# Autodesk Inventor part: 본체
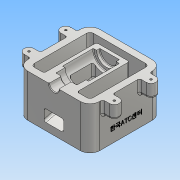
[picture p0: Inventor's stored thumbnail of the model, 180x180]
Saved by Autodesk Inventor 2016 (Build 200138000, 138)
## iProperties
Created: 2018-01
Part Number: 본체
Material: 알루미늄 6061
Document SubType Name: Modeling
Designer: Administrator
Density: 2.7 g/cm^3
Appearance: 알루미늄 - 평지
Mass: 995.217 g
Surface Area: 834.407 cm^2
Volume: 368.599 cm^3
Author: Administrator
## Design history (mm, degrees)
sketch "스케치1"
  geometry: L1 (-55, 55)-(55, 55); L2 (55, 55)-(55, -55); L3 (55, -55)-(-55, -55); L4 (-55, -55)-(-55, 55); L5 (-55, 55)-(55, -55); L6 (55, 55)-(-55, -55); 1 further point
  constraints: 12 end point, 2 midpoint, 2 parallel, 1 horizontal, 1 perpendicular
  dimensions: "d0" = 110 distance of L2.end L3.end; "d1" = 110 distance of L1.end L2.end
extrude "돌출1" new body sketch "스케치1" distance "d2" = 65; taper "d3" = 0 deg
feature "쉘1" dims "d4" = 10
sketch "스케치2"
  geometry: L1 (55, 55)-(-55, 55) reference; L2 (-45, -45)-(45, -45) reference; L3 (-25, 35)-(25, 35); L4 (25, 35)-(25, -45); L5 (25, -45)-(-25, -45); L6 (-25, -45)-(-25, 35); 2 further points
  constraints: 8 end point, 2 parallel, 1 horizontal, 1 midpoint, 1 perpendicular, 1 point on line, 1 vertical alignment
  dimensions: "d5" = 50 distance between parallel lines of L6 L4; "d6" = 20 distance between parallel lines of L3 L1
extrude "돌출2" join sketch "스케치2" distance "d7" = 65; taper "d8" = 0 deg
sketch "스케치3"
  geometry: L1 (-55, 0)-(55, 0) reference; L2 (-45, 0)-(-45, 8.564); L3 (-45, 8.564)-(35, 30); L4 (35, 65)-(35, 0) reference; L5 (-55, 0)-(-55, 65) reference; 1 further point
  constraints: 4 end point, 2 point on line, 1 vertical
  dimensions: "d9" = 30 distance from line of L1 L3.end; "d10" = 105 deg angle of L2 L3; "d11" = 10 distance between parallel lines of L5 L2
extrude "돌출3" cut sketch "스케치3" stored distance "d12" = 50; taper "d13" = 0 deg
sketch "스케치4"
  geometry: L1 (25, 35)-(-25, 35) reference; L2 (0, 35)-(0, -55); L3 (55, -55)-(-55, -55) reference; L4 (0, -55)-(-7.5, -55); L5 (-7.5, -36)-(-16, -36); L6 (-16, -36)-(-16, -22); L7 (-16, -22)-(-20, -22); L8 (-20, -22)-(-20, 25); L9 (-20, 25)-(-15, 25); L10 (-15, 25)-(-15, 30); L11 (-15, 30)-(0, 30); L12 (-7.5, -55)-(-7.5, -36); L13 (0, -55)-(-7.5, -55); 1 further point
  constraints: 22 end point, 6 perpendicular, 2 midpoint, 2 point on line, 1 collinear, 1 horizontal, 1 vertical
  dimensions: "d14" = 40 diameter of L8 L2; "d15" = 15 diameter of L12 L2; "d16" = 32 diameter of L6 L2; "d17" = 19 distance of L4.end L5.start; "d18" = 14 distance of L5.end L6.end; "d19" = 47 distance of L7.end L8.end; "d20" = 5 distance of L9.end L10.end; "d21" = 30 diameter of L10 L2
revolve "회전1" sketch "스케치4" stored, may be unused: angle "d22" = 90 deg
sketch "스케치5"
  geometry: L1 (-55, 55)-(-55, -55) reference; L2 (-55, -55)-(-7.5, -55) reference; L3 (-55, -20.5)-(-65, -20.5); L4 (-65, -20.5)-(-65, -35.5); L5 (-65, -35.5)-(-55, -35.5); L6 (-55, -35.5)-(-55, -20.5); A1 r 7.5 centre (-65, -28) between (-65, -20.5) and (-65, -35.5); 1 further point
  constraints: 8 end point, 2 parallel, 2 point on circle, 1 centre point, 1 horizontal, 1 midpoint, 1 perpendicular, 1 point on line
  dimensions: "d23" = 27 distance from line of L2 A1.centre; "d24" = 10 distance from line of L1 A1.centre; "d25" = 7.5 radius of A1
extrude "돌출4" join sketch "스케치5" distance "d26" = 20; taper "d27" = 0 deg
sketch "스케치6"
  geometry: A1 r 7.5 centre (-65, -28) between (-65, -20.5) and (-65, -35.5) reference; 2 further points
  constraints: 1 coincident
hole "구멍1" sketch "스케치6" at (-65, -28) diameter "d28" = 3.242; stored, may be unused: countersink angle "d32" = 90 deg, drill point angle "d34" = 118 deg; dims "d29" = 9, "d30" = 4, "d31" = 2, "d33" = 11
sketch "스케치7"
  geometry: L1 (-55, 11.061)-(20, 31.157); L2 (-22, 45)-(25, 45) reference; L3 (-55, 0)-(-55, 65) reference; L4 (-55, 29.061)-(-17, 39.243); L5 (35, 30)-(-45, 8.564) reference; L6 (45, 0)-(-45, 0) reference; L7 (25, 45)-(25, 65) reference; L8 (-17, 39.243)-(-17, 67.919); L9 (20, 31.157)-(20, 67.919); L10 (20, 67.919)-(-17, 67.919); 1 further point
  constraints: 10 end point, 2 parallel, 2 point on line, 2 vertical, 1 perpendicular
  dimensions: "d38" = 18 distance of L1.start L4.start; "d39" = 5 distance between parallel lines of L5 L1; "d40" = 30 distance from line of L6 L5.start (derived); "d43" = 37 distance between parallel lines of L9 L8; "d44" = 5 distance between parallel lines of L7 L9
extrude "돌출5" cut sketch "스케치7" stored distance "d45" = 30; taper "d46" = 0 deg
sketch "스케치8"
  geometry: L1 (0, 0)-(-65, 0) reference; L2 (0, 110)-(0, 0) reference; 2 further points
  constraints: 1 other
  dimensions: "d47" = 55 distance from line of L1 point (-20, 55); "d48" = 20 distance from line of L2 point (-20, 55)
feature "엠보싱1" sketch "스케치8" dims "d0" = 110, "d1" = 110, "d49" = 0.5, "d50" = 0
fillet "모깎기1" dims "d51" = 15, "d52" = 5
fillet "모깎기6" dims "d57" = 3
fillet "모깎기7" dims "d58" = 3
fillet "모깎기11" dims "d68" = 3
fillet "모깎기12" dims "d69" = 3
fillet "모깎기13" dims "d70" = 1
chamfer "모따기3" distance "d71" = 1; stored, may be unused: second distance "d72" = 2, angle "d73" = 45 deg
fillet "모깎기14" dims "d74" = 3
node "솔리드1"
pattern_linear "직사각형 패턴1" dims "d37" = 56
mirror "대칭1"
